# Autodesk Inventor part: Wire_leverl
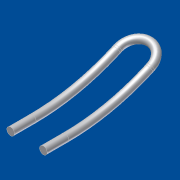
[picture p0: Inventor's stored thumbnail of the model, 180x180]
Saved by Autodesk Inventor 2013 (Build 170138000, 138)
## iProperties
Shininess: 69.0
Length Units: 11269
Angle Units: 11279
Time Units: 11290
Mass Units: 11283
Length Display Precision: 3
Angle Display Precision: 2
Created: 2001-04
Part Number: Wire_leverl
Material: Standard
Document SubType Name: Modellieren
Designer: dl
Density: 1 g/cm^3
Density: 0.0
Volumn: 0.0
Area: 0.0
PropertySet Name: Model Information
Control State: 0
Master: False
Checked Out: False
Author: dl
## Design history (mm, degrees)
body "Solid1"
sketch "Sketch1"
  geometry: C1 r 1.75 at (0, 0); 1 further point
  constraints: 1 centre point, 1 coincident
  dimensions: "d8" = 3.5 diameter of C1
sketch "3D-Skizze1" dims "d0" = 15, "d1" = -30, "d2" = 11.5, "d3" = -56, "d5" = 7.5, "d6" = 7.5
  geometry: L1 through (95, -9.928) direction (1, 0); L2 through (95, -9.928) direction (1, 0); 25 other entities
  constraints: 4 horizontal
  dimensions: "d4" = 95 dimension on L1; "d7" = 95 dimension on L2 (= d4)
sweep "Sweep1" dims "d9" = 0
workplane "Work Plane1"
workplane "Work Plane2"
workplane "Work Plane3"
workplane "Work Plane4"
workaxis "Work Axis1"
workpoint "Work Point1"
workpoint "Work Point2"
workaxis "Work Axis2"
workpoint "Work Point3"
workpoint "Work Point4"
workaxis "Work Axis3"
workaxis "Work Axis4"
workaxis "Work Axis5"
workpoint "Work Point5"
workpoint "Work Point6"
